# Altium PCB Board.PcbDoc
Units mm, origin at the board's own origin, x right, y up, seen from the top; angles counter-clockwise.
Board outline 30 x 20 mm, 2 copper layers (Top, Bottom), stack 0 mm thick; 2 components, 1 nets, 0 pads, 0 vias.
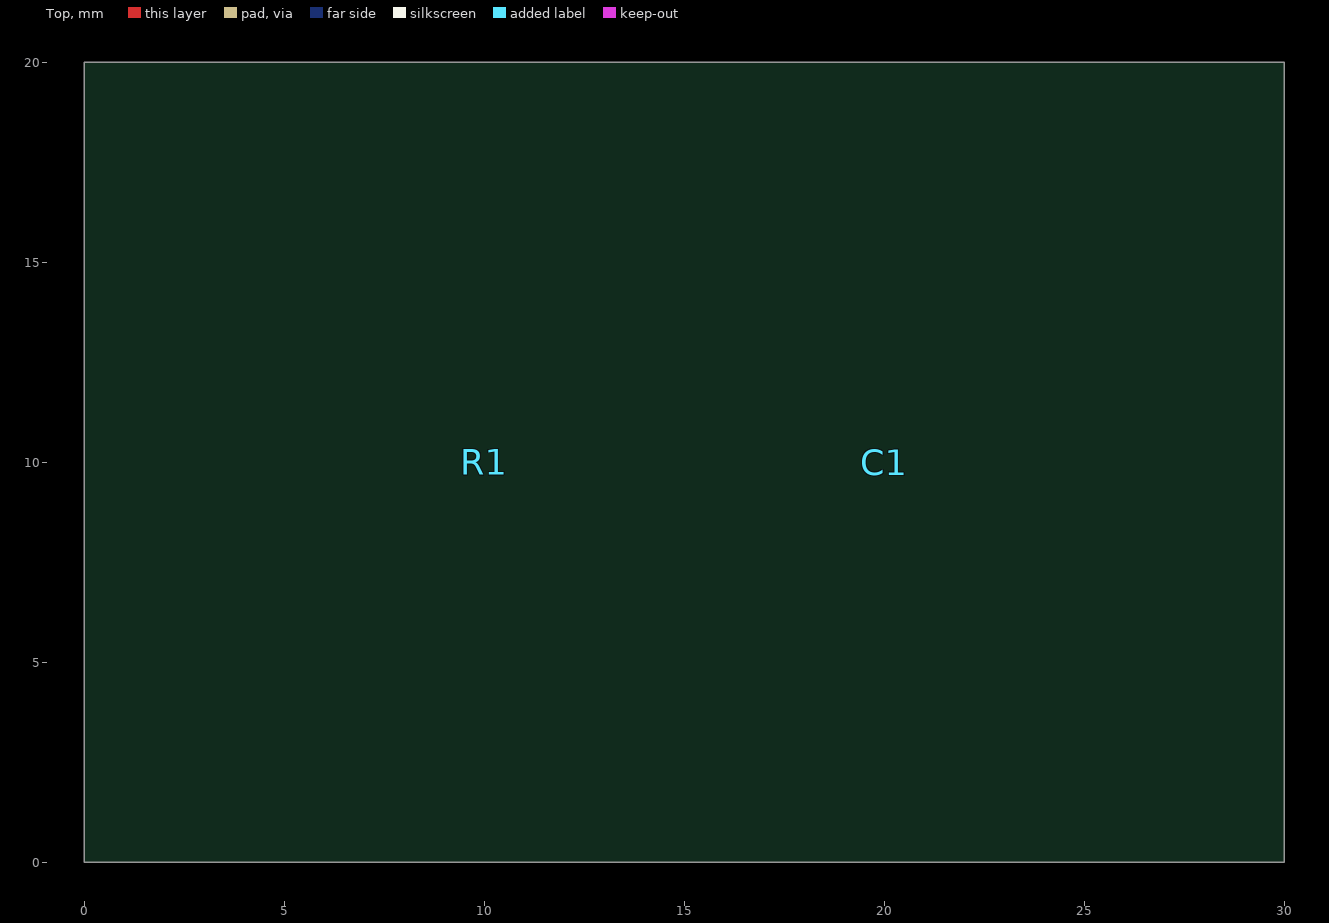
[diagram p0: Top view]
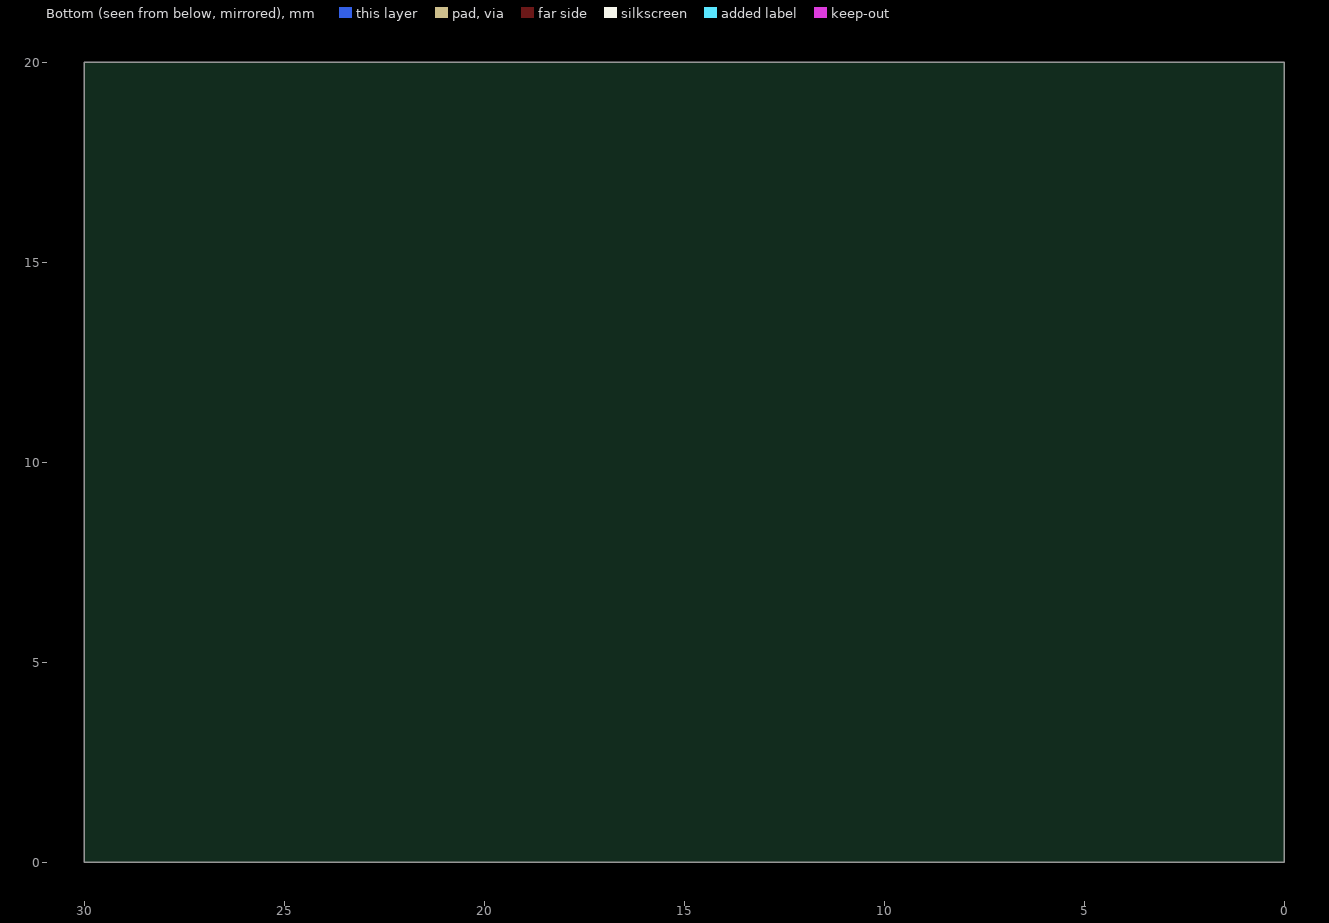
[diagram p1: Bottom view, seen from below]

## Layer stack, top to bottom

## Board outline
0,0 30,0 30,20 0,20

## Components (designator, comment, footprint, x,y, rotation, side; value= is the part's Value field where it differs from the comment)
C1 "" C0402 20,10 r0 top
R1 "" R0603 10,10 r0 top

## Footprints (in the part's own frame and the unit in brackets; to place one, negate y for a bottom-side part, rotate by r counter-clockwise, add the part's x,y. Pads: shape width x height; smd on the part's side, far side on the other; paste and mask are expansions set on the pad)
C0402 [mm]
R0603 [mm]

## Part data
C1: library part Cap
R1: library part Res

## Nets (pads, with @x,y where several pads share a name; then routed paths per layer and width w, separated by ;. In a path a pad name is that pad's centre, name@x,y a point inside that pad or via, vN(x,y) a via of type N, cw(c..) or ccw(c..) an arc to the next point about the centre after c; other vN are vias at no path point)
GND: 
